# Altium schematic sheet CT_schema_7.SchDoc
size 374 x 245 mm
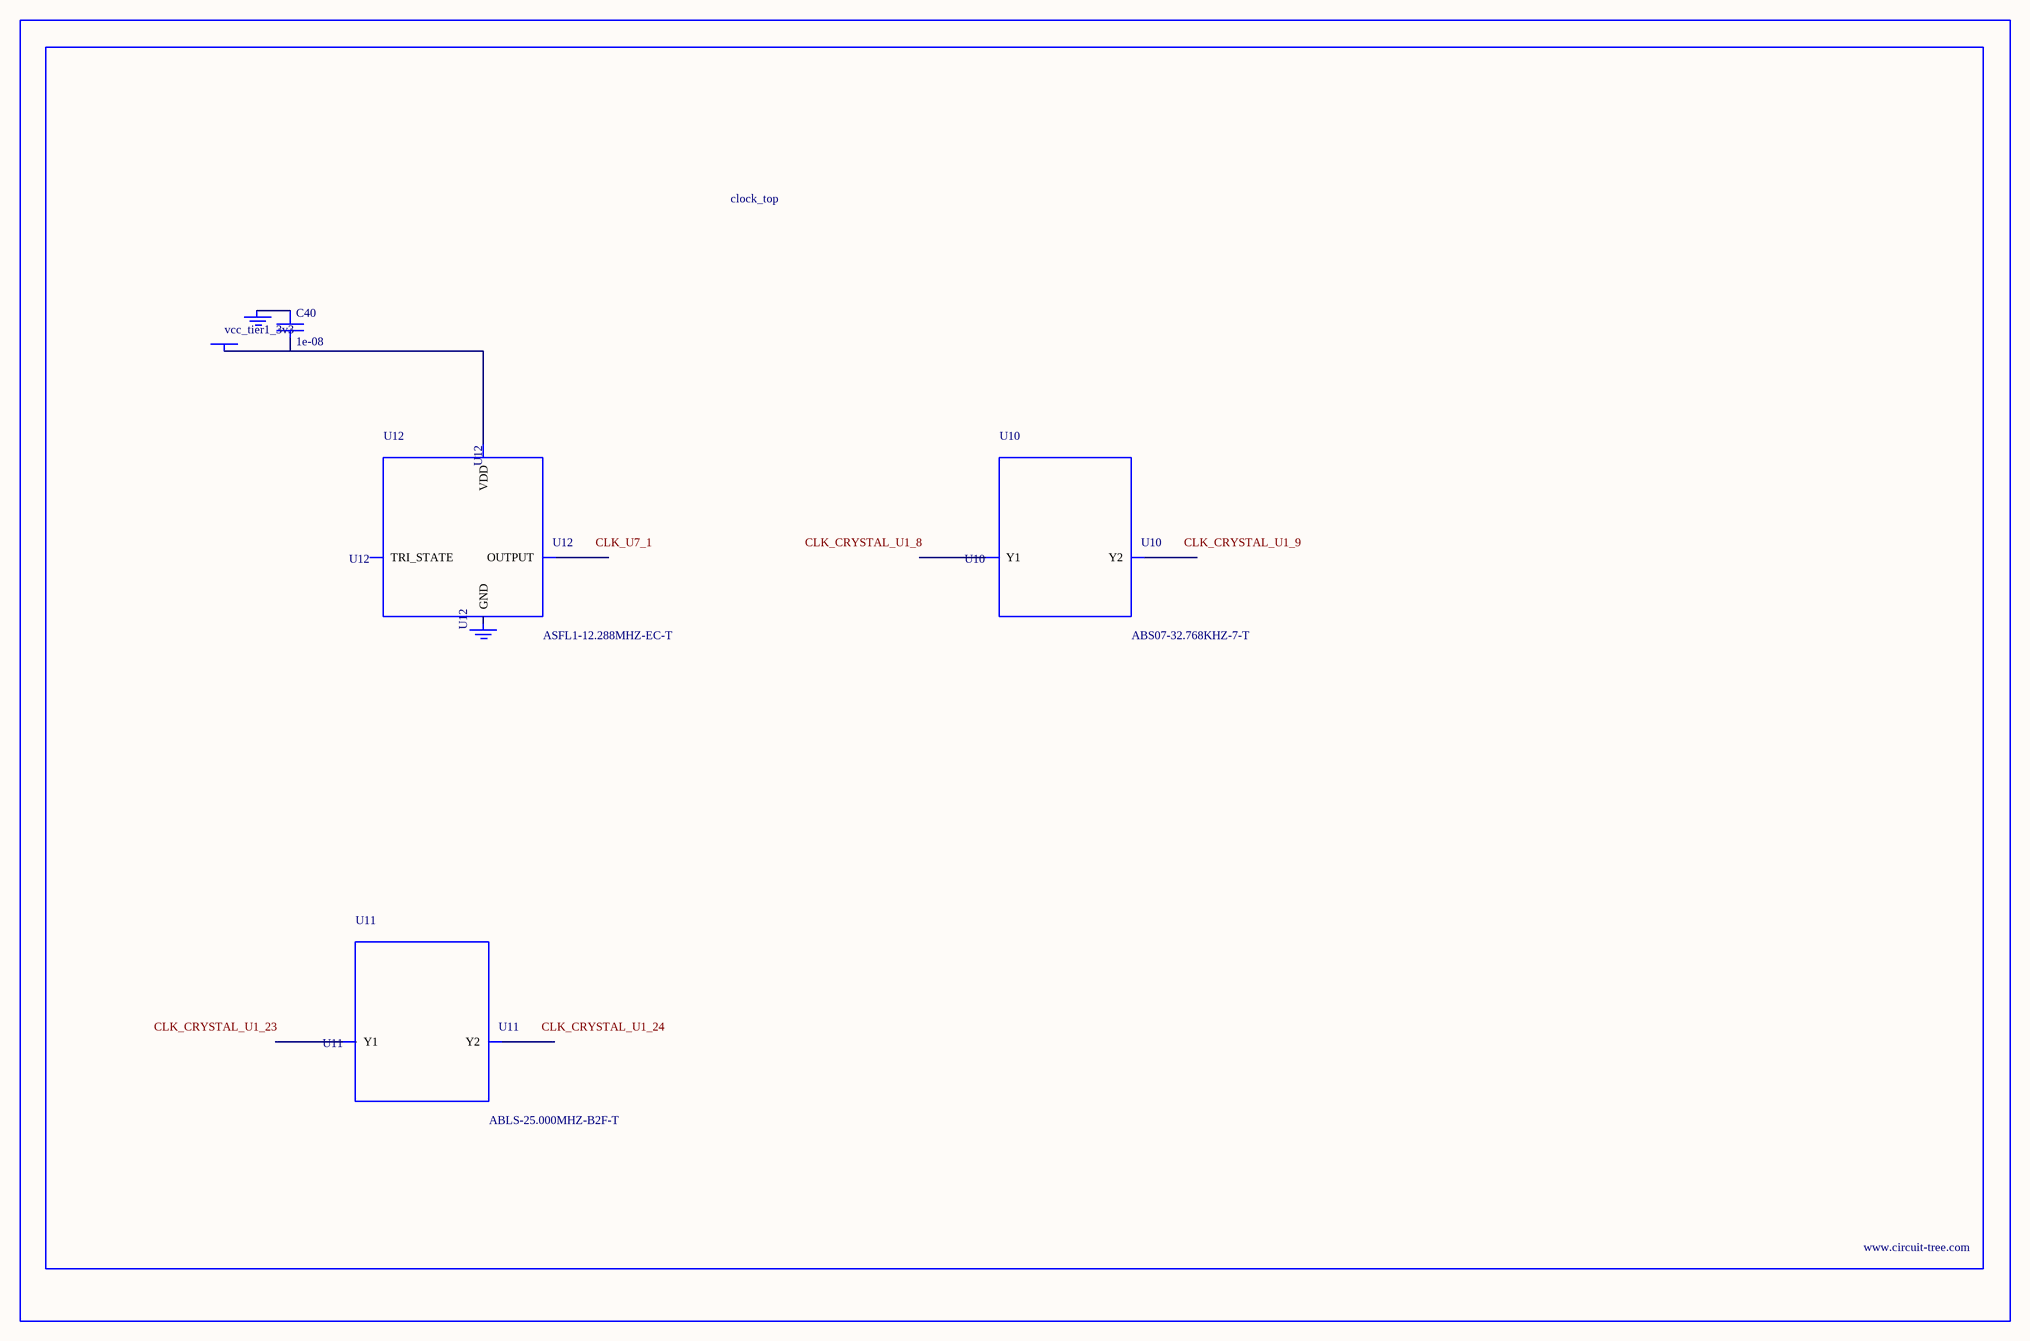
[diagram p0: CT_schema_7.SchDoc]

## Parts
BORDER6  (no value)
C40  1e-08  [C0402]
GND_INSTANCE_6_0  (no value)
GND_INSTANCE_6_1  (no value)
POWER_INSTANCE_6_0  vcc_tier1_3v3
U10  ABS07-32.768KHZ-7-T  [ABS07-32.768KHZ-7-T]
U11  ABLS-25.000MHZ-B2F-T  [ABLS-25.000MHZ-B2F-T]
U12  ASFL1-12.288MHZ-EC-T  [ASFL1]

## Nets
NetC40_1: C40.1 GND_INSTANCE_6_0.0(GND)
NetC40_2: C40.2 POWER_INSTANCE_6_0.0(PWR) U12.4(VDD)

Not connected (* = marked no-connect by the designer): GND_INSTANCE_6_1 0(GND); U10 1(Y1) 2(Y2); U11 1(Y1) 2(Y2); U12 1(TRI_STATE) 2(GND) 3(OUTPUT)

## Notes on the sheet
- Labels drawn without touching a wire or pin: CLK_CRYSTAL_U1_8, CLK_CRYSTAL_U1_9, CLK_CRYSTAL_U1_23, CLK_CRYSTAL_U1_24, CLK_U7_1

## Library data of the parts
BORDER6 = BORDER_PAGE6
C40 = C0402C103K3RAC
GND_INSTANCE_6_0 GND_INSTANCE_6_1 = GND
POWER_INSTANCE_6_0 = PWR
